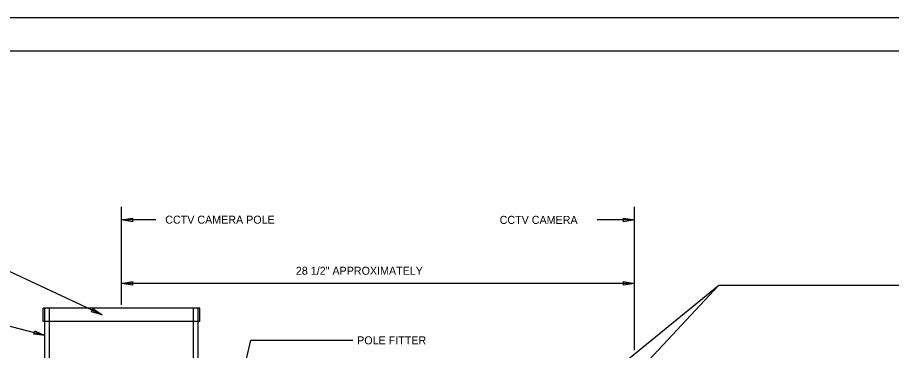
# Model space of a CAD drawing. Extents: x 1299104.6 to 1299141.4, y 239713.3 to 239735.3.
# Drawn here: x 1299115.78 to 1299128.87, y 239730.29 to 239735.27 of the extents above; entities that cross this region are included whole.
import ezdxf

# ---------------------------------------------------------------- set-up
doc = ezdxf.new("R2010")
doc.units = 0
for name, color, linetype in [('DIM TXT', 7, 'Continuous'), ('GS_plotshape_p', 7, 'Continuous'), ('Level 1', 7, 'Continuous'), ('Level 3', 7, 'Continuous'), ('Level 8', 7, 'Continuous')]:
    doc.layers.add(name, color=color, linetype=linetype)

msp = doc.modelspace()

# ---------------------------------------------------------------- linework, layer by layer
at = {"layer": 'GS_plotshape_p'}
msp.add_lwpolyline([(1299104.622, 239735.273), (1299138.622, 239735.273), (1299138.622, 239713.273), (1299104.622, 239713.273)], close=True, dxfattribs=at)
at = {"layer": 'Level 1'}
msp.add_lwpolyline([(1299138.122, 239713.773), (1299106.122, 239713.773), (1299106.122, 239734.773), (1299138.122, 239734.773)], close=True, dxfattribs=at)
at = {"layer": 'Level 3'}
for p, q in [((1299116.16, 239730.718), (1299116.16, 239730.92)), ((1299118.509, 239730.92), (1299116.16, 239730.92)), ((1299116.187, 239729.3), (1299116.187, 239730.92)), ((1299116.254, 239729.368), (1299116.254, 239730.92)), ((1299118.482, 239730.92), (1299116.927, 239730.92)), ((1299118.482, 239730.92), (1299118.414, 239730.92)), ((1299118.414, 239729.368), (1299118.414, 239730.92)), ((1299118.482, 239729.3), (1299118.482, 239730.92)), ((1299118.509, 239730.718), (1299118.509, 239730.92)), ((1299118.509, 239730.718), (1299116.16, 239730.718))]:
    msp.add_line(p, q, dxfattribs=at)
at = {"layer": 'Level 8'}
for p, q in [((1299117.334, 239730.97), (1299117.334, 239732.435)), ((1299125.024, 239730.291), (1299125.024, 239732.435)), ((1299117.85, 239732.243), (1299117.334, 239732.243)), ((1299125.024, 239732.243), (1299124.463, 239732.243)), ((1299125.024, 239731.291), (1299117.334, 239731.291))]:
    msp.add_line(p, q, dxfattribs=at)
for points in [[(1299117.501, 239732.27), (1299117.501, 239732.215), (1299117.334, 239732.243)], [(1299124.858, 239732.215), (1299124.858, 239732.27), (1299125.024, 239732.243)], [(1299117.501, 239731.318), (1299117.501, 239731.264), (1299117.334, 239731.291)], [(1299124.858, 239731.264), (1299124.858, 239731.318), (1299125.024, 239731.291)], [(1299116.883, 239730.867), (1299116.906, 239730.916), (1299117.045, 239730.819)], [(1299116.019, 239730.529), (1299116.034, 239730.582), (1299116.186, 239730.508)]]:
    msp.add_lwpolyline(points, close=True, dxfattribs=at)
for points in [[(1299117.045, 239730.819), (1299117.045, 239730.819), (1299114.668, 239731.926), (1299111.506, 239731.926)], [(1299123.113, 239728.677), (1299123.113, 239728.677), (1299126.285, 239731.263), (1299132.012, 239731.263)], [(1299123.904, 239728.712), (1299126.285, 239731.263), (1299132.049, 239731.263)], [(1299116.186, 239730.508), (1299116.186, 239730.508), (1299113.474, 239731.216), (1299111.987, 239731.214)], [(1299118.843, 239728.585), (1299119.272, 239730.443), (1299120.802, 239730.443)]]:
    msp.add_lwpolyline(points, dxfattribs=at)

# ---------------------------------------------------------------- texts
at = {"layer": 'DIM TXT'}
for s, p in [('  CCTV CAMERA POLE', (1299117.901, 239732.185)), ('  CCTV CAMERA', (1299122.912, 239732.182)), ('28 1/2" APPROXIMATELY', (1299119.948, 239731.42)), ('POLE FITTER', (1299120.866, 239730.378))]:
    msp.add_text(s, height=0.12, dxfattribs=at).set_placement(p)

doc.saveas('drawing.dxf')
